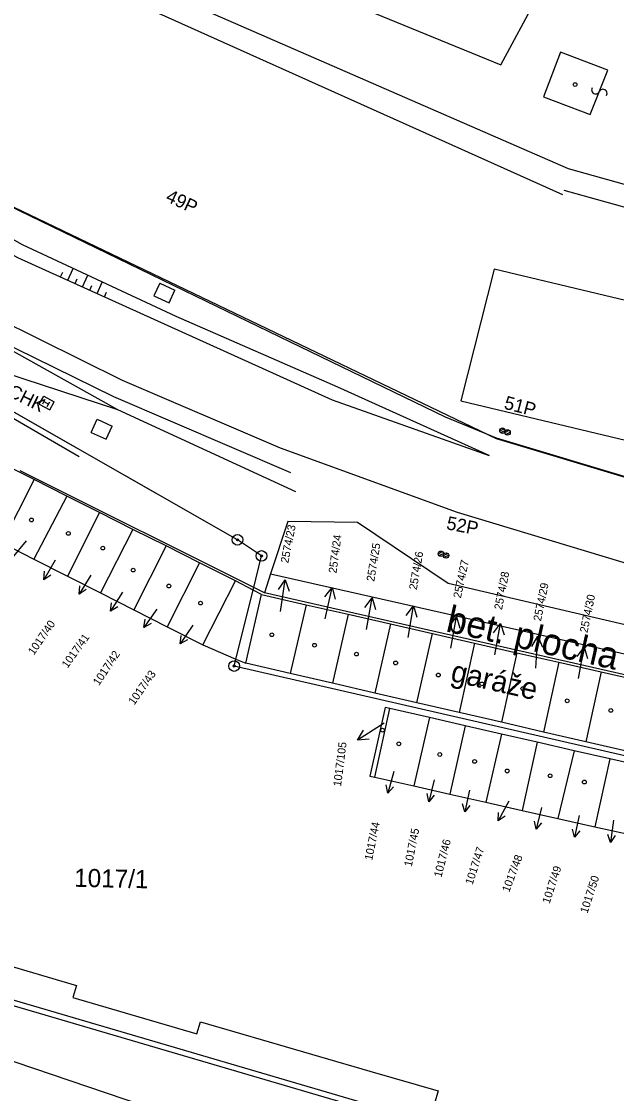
# Model space of a CAD drawing. Extents: x -469926 to -462499, y -1098642 to -1092733.
# Drawn here: x -465329.9 to -465274.2, y -1095180.8 to -1095080.4 of the extents above; entities that cross this region are included whole.
import ezdxf

# ---------------------------------------------------------------- set-up
doc = ezdxf.new("R2010")
doc.units = 0
for name, color, linetype in [('Vrstva 1', 7, 'Continuous'), ('Vrstva 10', 7, 'Continuous'), ('Vrstva 11', 7, 'Continuous'), ('Vrstva 12', 7, 'Continuous'), ('Vrstva 13', 7, 'Continuous'), ('Vrstva 16', 7, 'Continuous'), ('Vrstva 24', 7, 'Continuous'), ('Vrstva 25', 7, 'Continuous'), ('Vrstva 29', 7, 'Continuous'), ('Vrstva 4', 7, 'Continuous'), ('Vrstva 40', 7, 'Continuous'), ('Vrstva 42', 7, 'Continuous'), ('Vrstva 48', 7, 'Continuous'), ('Vrstva 50', 7, 'Continuous'), ('Vrstva 51', 7, 'Continuous'), ('Vrstva 6', 7, 'Continuous'), ('Vrstva 60', 7, 'Continuous'), ('Vrstva 8', 7, 'Continuous'), ('Vrstva 9', 7, 'Continuous')]:
    doc.layers.add(name, color=color, linetype=linetype)

msp = doc.modelspace()

# ---------------------------------------------------------------- linework, layer by layer
at = {"layer": 'Vrstva 1'}
for p, q in [((-465285.45, -1095119.46), (-465346.23, -1095090.29)), ((-465285.68, -1095103.56), (-465288.78, -1095115.91)), ((-465249.74, -1095112.21), (-465285.68, -1095103.56)), ((-465309.7, -1095128.93), (-465352.37, -1095104.57)), ((-465288.78, -1095115.91), (-465252.8, -1095124.51)), ((-465266.34, -1095125.23), (-465285.45, -1095119.46)), ((-465328.75, -1095123.29), (-465331.8, -1095121.75)), ((-465328.75, -1095123.29), (-465331.74, -1095129.22)), ((-465325.67, -1095124.83), (-465328.75, -1095123.29)), ((-465325.67, -1095124.83), (-465328.76, -1095130.73)), ((-465322.62, -1095126.37), (-465325.67, -1095124.83)), ((-465322.62, -1095126.37), (-465325.61, -1095132.34)), ((-465319.49, -1095127.95), (-465322.62, -1095126.37)), ((-465319.49, -1095127.95), (-465322.52, -1095133.91)), ((-465316.38, -1095129.51), (-465319.49, -1095127.95)), ((-465331.74, -1095129.22), (-465328.76, -1095130.73)), ((-465316.38, -1095129.51), (-465319.41, -1095135.49)), ((-465313.26, -1095131.08), (-465316.38, -1095129.51)), ((-465307.46, -1095130.44), (-465309.7, -1095128.93)), ((-465308.25, -1095133.64), (-465307.46, -1095130.44)), ((-465328.76, -1095130.73), (-465325.61, -1095132.34)), ((-465313.26, -1095131.08), (-465316.3, -1095137.07)), ((-465309.89, -1095132.78), (-465313.26, -1095131.08)), ((-465325.61, -1095132.34), (-465322.52, -1095133.91)), ((-465312.94, -1095138.78), (-465309.89, -1095132.78)), ((-465309.86, -1095140.1), (-465308.25, -1095133.64)), ((-465322.52, -1095133.91), (-465319.41, -1095135.49)), ((-465308.93, -1095140.5), (-465307.45, -1095134.06)), ((-465307.45, -1095134.06), (-465303.28, -1095135.01)), ((-465319.41, -1095135.49), (-465316.3, -1095137.07)), ((-465303.28, -1095135.01), (-465304.76, -1095141.46)), ((-465303.28, -1095135.01), (-465299.33, -1095135.91)), ((-465299.33, -1095135.91), (-465300.81, -1095142.37)), ((-465299.33, -1095135.91), (-465295.39, -1095136.81)), ((-465316.3, -1095137.07), (-465312.94, -1095138.78)), ((-465295.39, -1095136.81), (-465296.86, -1095143.29)), ((-465295.39, -1095136.81), (-465291.45, -1095137.71)), ((-465292.9, -1095144.2), (-465291.45, -1095137.71)), ((-465291.45, -1095137.71), (-465287.5, -1095138.61)), ((-465287.5, -1095138.61), (-465288.95, -1095145.11)), ((-465287.5, -1095138.61), (-465283.56, -1095139.51)), ((-465283.56, -1095139.51), (-465285, -1095146.02)), ((-465283.56, -1095139.51), (-465279.61, -1095140.41)), ((-465310.02, -1095140.76), (-465309.86, -1095140.1)), ((-465304.76, -1095141.46), (-465308.93, -1095140.5)), ((-465279.61, -1095140.41), (-465281.05, -1095146.94)), ((-465279.61, -1095140.41), (-465275.67, -1095141.31)), ((-465219.72, -1095161.52), (-465310.02, -1095140.76)), ((-465300.81, -1095142.37), (-465304.76, -1095141.46)), ((-465275.67, -1095141.31), (-465277.1, -1095147.85)), ((-465275.67, -1095141.31), (-465271.73, -1095142.21)), ((-465296.86, -1095143.29), (-465300.81, -1095142.37)), ((-465292.9, -1095144.2), (-465296.86, -1095143.29)), ((-465295.87, -1095144.64), (-465297.3, -1095151.07)), ((-465295.43, -1095144.74), (-465295.87, -1095144.64)), ((-465288.95, -1095145.11), (-465292.9, -1095144.2)), ((-465296.86, -1095151.17), (-465295.43, -1095144.74)), ((-465291.73, -1095145.59), (-465295.43, -1095144.74)), ((-465291.73, -1095145.59), (-465293.2, -1095151.99)), ((-465288.38, -1095146.35), (-465291.73, -1095145.59)), ((-465285, -1095146.02), (-465288.95, -1095145.11)), ((-465288.38, -1095146.35), (-465289.82, -1095152.76)), ((-465285, -1095147.13), (-465288.38, -1095146.35)), ((-465281.05, -1095146.94), (-465285, -1095146.02)), ((-465285, -1095147.13), (-465286.44, -1095153.52)), ((-465281.65, -1095147.89), (-465285, -1095147.13)), ((-465277.1, -1095147.85), (-465281.05, -1095146.94)), ((-465281.65, -1095147.89), (-465283.04, -1095154.29)), ((-465278.19, -1095148.69), (-465281.65, -1095147.89)), ((-465278.19, -1095148.69), (-465279.7, -1095155.04)), ((-465278.19, -1095148.69), (-465279.7, -1095155.04)), ((-465274.83, -1095149.46), (-465278.19, -1095148.69)), ((-465274.83, -1095149.46), (-465278.19, -1095148.69)), ((-465273.15, -1095148.76), (-465277.1, -1095147.85)), ((-465273.15, -1095148.76), (-465277.1, -1095147.85)), ((-465274.83, -1095149.46), (-465276.24, -1095155.82)), ((-465274.83, -1095149.46), (-465276.24, -1095155.82)), ((-465271.43, -1095150.24), (-465274.83, -1095149.46)), ((-465271.43, -1095150.24), (-465274.83, -1095149.46)), ((-465297.3, -1095151.07), (-465296.86, -1095151.17)), ((-465296.86, -1095151.17), (-465293.2, -1095151.99)), ((-465293.2, -1095151.99), (-465289.82, -1095152.76)), ((-465289.82, -1095152.76), (-465286.44, -1095153.52)), ((-465286.44, -1095153.52), (-465283.04, -1095154.29)), ((-465283.04, -1095154.29), (-465279.7, -1095155.04)), ((-465283.04, -1095154.29), (-465279.7, -1095155.04)), ((-465279.7, -1095155.04), (-465276.24, -1095155.82)), ((-465279.7, -1095155.04), (-465276.24, -1095155.82)), ((-465276.24, -1095155.82), (-465272.83, -1095156.59)), ((-465276.24, -1095155.82), (-465272.83, -1095156.59)), ((-465336.84, -1095167.15), (-465324.77, -1095170.68)), ((-465324.77, -1095170.68), (-465325.11, -1095171.83)), ((-465325.11, -1095171.83), (-465313.51, -1095175.23)), ((-465313.51, -1095175.23), (-465313.17, -1095174.09)), ((-465313.51, -1095175.23), (-465313.17, -1095174.09)), ((-465313.17, -1095174.09), (-465306.75, -1095175.96)), ((-465313.17, -1095174.09), (-465306.75, -1095175.96)), ((-465306.75, -1095175.96), (-465297.32, -1095178.72)), ((-465306.75, -1095175.96), (-465297.32, -1095178.72)), ((-465297.32, -1095178.72), (-465290.92, -1095180.57)), ((-465297.32, -1095178.72), (-465290.92, -1095180.57)), ((-465290.92, -1095180.57), (-465291.27, -1095181.74)), ((-465290.92, -1095180.57), (-465291.27, -1095181.74))]:
    msp.add_line(p, q, dxfattribs=at)
at = {"layer": 'Vrstva 10'}
msp.add_lwpolyline([(-465135.98, -1095170.77), (-465139.71, -1095170.75), (-465139.73, -1095170.89), (-465144.3, -1095170.27), (-465144.4, -1095170.93), (-465145.96, -1095170.72), (-465150.93, -1095170.7), (-465150.93, -1095170.7), (-465150.93, -1095170.7), (-465207.61, -1095162.89), (-465219.72, -1095161.52), (-465219.72, -1095161.52), (-465219.72, -1095161.52), (-465310.02, -1095140.76), (-465308.25, -1095133.64), (-465307.46, -1095130.44), (-465309.7, -1095128.93), (-465352.37, -1095104.57)], dxfattribs=at)
at = {"layer": 'Vrstva 11'}
for p, q in [((-465316.99, -1095104.89), (-465317.53, -1095106.08)), ((-465316.99, -1095104.89), (-465315.58, -1095105.54)), ((-465317.53, -1095106.08), (-465316.1, -1095106.73)), ((-465316.1, -1095106.73), (-465315.58, -1095105.54)), ((-465328.26, -1095116.21), (-465327.85, -1095115.46)), ((-465327.85, -1095115.46), (-465326.86, -1095116.01)), ((-465328.26, -1095116.21), (-465327.27, -1095116.75)), ((-465327.94, -1095116.19), (-465327.7, -1095115.76)), ((-465327.82, -1095115.98), (-465327.38, -1095116.22)), ((-465327.51, -1095116.44), (-465327.26, -1095116)), ((-465327.27, -1095116.75), (-465326.86, -1095116.01)), ((-465323.4, -1095118.86), (-465322.85, -1095117.63)), ((-465322.85, -1095117.63), (-465321.44, -1095118.27)), ((-465322, -1095119.5), (-465321.44, -1095118.27)), ((-465285.14, -1095118.72), (-465284.75, -1095118.52)), ((-465323.4, -1095118.86), (-465322, -1095119.5)), ((-465285.07, -1095118.89), (-465284.65, -1095118.68)), ((-465284.67, -1095118.87), (-465284.27, -1095118.67)), ((-465284.6, -1095119.05), (-465284.17, -1095118.83)), ((-465290.91, -1095130.24), (-465290.51, -1095130.04)), ((-465290.84, -1095130.41), (-465290.41, -1095130.2)), ((-465290.43, -1095130.4), (-465290.03, -1095130.2)), ((-465290.36, -1095130.57), (-465289.94, -1095130.36))]:
    msp.add_line(p, q, dxfattribs=at)
for centre in [(-465284.9, -1095118.71), (-465284.9, -1095118.71), (-465284.42, -1095118.87), (-465284.42, -1095118.87), (-465290.66, -1095130.24), (-465290.66, -1095130.24), (-465290.18, -1095130.4), (-465290.18, -1095130.4)]:
    msp.add_circle(centre, 0.25, dxfattribs=at)
at = {"layer": 'Vrstva 12'}
for p, q in [((-465312.61, -1095106.59), (-465340.64, -1095093.02)), ((-465290.24, -1095117.45), (-465312.61, -1095106.59)), ((-465285.45, -1095119.42), (-465290.24, -1095117.45)), ((-465266.36, -1095125.13), (-465285.45, -1095119.42))]:
    msp.add_line(p, q, dxfattribs=at)
at = {"layer": 'Vrstva 13'}
for p, q in [((-465304.98, -1095127.21), (-465306.61, -1095132.13)), ((-465298.47, -1095127.31), (-465304.98, -1095127.21)), ((-465289.98, -1095133.04), (-465298.47, -1095127.31)), ((-465306.61, -1095132.13), (-465307.17, -1095133.91)), ((-465306.61, -1095132.13), (-465232.1, -1095148.97)), ((-465231.51, -1095146.66), (-465289.98, -1095133.04))]:
    msp.add_line(p, q, dxfattribs=at)
at = {"layer": 'Vrstva 16'}
for p, q in [((-465329.5, -1095129.02), (-465330.82, -1095130.65)), ((-465326.77, -1095130.85), (-465327.83, -1095132.67)), ((-465323.43, -1095132.23), (-465324.53, -1095134.02)), ((-465305.67, -1095135.64), (-465305.23, -1095132.67)), ((-465301.51, -1095136.32), (-465300.83, -1095133.4)), ((-465320.46, -1095133.83), (-465321.58, -1095135.61)), ((-465297.64, -1095137.33), (-465297.11, -1095134.38)), ((-465317.24, -1095135.44), (-465318.47, -1095137.14)), ((-465293.72, -1095138.07), (-465293.24, -1095135.11)), ((-465289.73, -1095139.09), (-465289.2, -1095136.14)), ((-465313.9, -1095136.93), (-465315.06, -1095138.68)), ((-465285.6, -1095139.71), (-465285.07, -1095136.76)), ((-465281.76, -1095140.96), (-465281.59, -1095137.97)), ((-465277.77, -1095141.93), (-465277.24, -1095138.98)), ((-465295.96, -1095146.1), (-465298.48, -1095147.72)), ((-465295.07, -1095150.63), (-465295.62, -1095152.66)), ((-465291.28, -1095151.43), (-465291.79, -1095153.47)), ((-465287.99, -1095152.38), (-465288.43, -1095154.43)), ((-465284.29, -1095153.42), (-465285.29, -1095155.27)), ((-465284.29, -1095153.42), (-465285.29, -1095155.27)), ((-465281.24, -1095154.01), (-465281.73, -1095156.05)), ((-465281.24, -1095154.01), (-465281.73, -1095156.05)), ((-465277.71, -1095154.75), (-465278.15, -1095156.8)), ((-465277.71, -1095154.75), (-465278.15, -1095156.8)), ((-465274.5, -1095155.2), (-465274.78, -1095157.28)), ((-465274.5, -1095155.2), (-465274.78, -1095157.28))]:
    msp.add_line(p, q, dxfattribs=at)
for points in [[(-465327.17, -1095132.24), (-465327.83, -1095132.67), (-465327.78, -1095131.88)], [(-465323.87, -1095133.6), (-465324.53, -1095134.02), (-465324.46, -1095133.24)], [(-465305.87, -1095133.59), (-465305.23, -1095132.67), (-465304.88, -1095133.74)], [(-465301.54, -1095134.26), (-465300.83, -1095133.4), (-465300.57, -1095134.49)], [(-465297.78, -1095135.27), (-465297.11, -1095134.38), (-465296.79, -1095135.45)], [(-465320.91, -1095135.2), (-465321.58, -1095135.61), (-465321.5, -1095134.83)], [(-465293.9, -1095136.02), (-465293.24, -1095135.11), (-465292.91, -1095136.18)], [(-465317.78, -1095136.78), (-465318.47, -1095137.14), (-465318.34, -1095136.37)], [(-465289.87, -1095137.03), (-465289.2, -1095136.14), (-465288.88, -1095137.21)], [(-465285.74, -1095137.65), (-465285.07, -1095136.76), (-465284.75, -1095137.83)], [(-465314.38, -1095138.29), (-465315.06, -1095138.68), (-465314.97, -1095137.9)], [(-465282.15, -1095138.94), (-465281.59, -1095137.97), (-465281.15, -1095138.99)], [(-465277.91, -1095139.87), (-465277.24, -1095138.98), (-465276.92, -1095140.05)], [(-465297.37, -1095147.6), (-465298.48, -1095147.72), (-465297.91, -1095146.76)], [(-465295.1, -1095152.07), (-465295.62, -1095152.66), (-465295.77, -1095151.89)], [(-465291.28, -1095152.87), (-465291.79, -1095153.47), (-465291.96, -1095152.7)], [(-465287.94, -1095153.82), (-465288.43, -1095154.43), (-465288.63, -1095153.68)], [(-465284.65, -1095154.82), (-465285.29, -1095155.27), (-465285.26, -1095154.49)], [(-465284.65, -1095154.82), (-465285.29, -1095155.27), (-465285.26, -1095154.49)], [(-465281.23, -1095155.45), (-465281.73, -1095156.05), (-465281.91, -1095155.29)], [(-465281.23, -1095155.45), (-465281.73, -1095156.05), (-465281.91, -1095155.29)], [(-465277.66, -1095156.19), (-465278.15, -1095156.8), (-465278.35, -1095156.04)], [(-465277.66, -1095156.19), (-465278.15, -1095156.8), (-465278.35, -1095156.04)], [(-465274.34, -1095156.63), (-465274.78, -1095157.28), (-465275.04, -1095156.54)], [(-465274.34, -1095156.63), (-465274.78, -1095157.28), (-465275.04, -1095156.54)]]:
    msp.add_lwpolyline(points, dxfattribs=at)
at = {"layer": 'Vrstva 24'}
for centre, radius in [((-465309.7, -1095128.93), 0.5), ((-465309.7, -1095128.93), 0.1), ((-465307.46, -1095130.44), 0.5), ((-465307.46, -1095130.44), 0.1), ((-465310.02, -1095140.76), 0.5), ((-465310.02, -1095140.76), 0.1)]:
    msp.add_circle(centre, radius, dxfattribs=at)
at = {"layer": 'Vrstva 25'}
for centre in [(-465329, -1095127.07), (-465325.54, -1095128.33), (-465322.32, -1095129.71), (-465319.47, -1095131.77), (-465316.13, -1095133.26), (-465313.16, -1095134.86), (-465306.48, -1095137.83), (-465302.49, -1095138.81), (-465298.57, -1095139.64), (-465294.9, -1095140.47), (-465290.9, -1095141.6), (-465286.83, -1095142.43), (-465282.99, -1095142.88), (-465278.83, -1095144.02), (-465274.75, -1095144.92), (-465296.12, -1095146.77), (-465294.6, -1095148.05), (-465290.77, -1095149.05), (-465287.5, -1095149.7), (-465284.45, -1095150.59), (-465280.44, -1095151.04), (-465280.44, -1095151.04), (-465277.23, -1095151.63), (-465277.23, -1095151.63)]:
    msp.add_circle(centre, 0.175, dxfattribs=at)
at = {"layer": 'Vrstva 29'}
msp.add_circle((-465278.1, -1095086.27), 0.175, dxfattribs=at)
at = {"layer": 'Vrstva 4'}
for p, q in [((-465310.53, -1095073.95), (-465285.06, -1095084.43)), ((-465285.06, -1095084.43), (-465280.07, -1095075.13)), ((-465279.46, -1095083.24), (-465281.05, -1095087.41)), ((-465275.04, -1095084.93), (-465279.46, -1095083.24)), ((-465276.67, -1095089.08), (-465275.04, -1095084.93)), ((-465281.05, -1095087.41), (-465276.67, -1095089.08)), ((-465308.25, -1095133.64), (-465309.89, -1095132.78)), ((-465307.45, -1095134.06), (-465308.25, -1095133.64)), ((-465312.94, -1095138.78), (-465309.86, -1095140.1)), ((-465309.86, -1095140.1), (-465308.93, -1095140.5)), ((-465189.34, -1095214.13), (-465355.8, -1095165.21))]:
    msp.add_line(p, q, dxfattribs=at)
at = {"layer": 'Vrstva 40'}
for p, q in [((-465339.74, -1095067.5), (-465278.76, -1095094.15)), ((-465278.76, -1095094.15), (-465241.79, -1095104.38))]:
    msp.add_line(p, q, dxfattribs=at)
at = {"layer": 'Vrstva 42'}
for p, q in [((-465279.24, -1095096.59), (-465339.95, -1095069.31)), ((-465241.12, -1095106.74), (-465279.11, -1095096.2))]:
    msp.add_line(p, q, dxfattribs=at)
at = {"layer": 'Vrstva 48'}
for p, q in [((-465326.26, -1095104.29), (-465326.06, -1095103.85)), ((-465325.58, -1095104.6), (-465325.09, -1095103.51)), ((-465324.9, -1095104.91), (-465324.7, -1095104.48)), ((-465324.21, -1095105.22), (-465323.73, -1095104.14)), ((-465323.53, -1095105.53), (-465323.34, -1095105.1)), ((-465322.85, -1095105.84), (-465322.37, -1095104.78)), ((-465322.16, -1095106.15), (-465321.97, -1095105.73))]:
    msp.add_line(p, q, dxfattribs=at)
at = {"layer": 'Vrstva 51'}
for centre, radius, start, end in [((-465276.17, -1095086.77), 0.376, 148.4604, 334.7715), ((-465275.48, -1095087.09), 0.377, 327.7843, 155.4475)]:
    msp.add_arc(centre, radius, start, end, dxfattribs=at)
at = {"layer": 'Vrstva 6'}
for p, q in [((-465307.17, -1095133.91), (-465330.06, -1095122.47)), ((-465232.58, -1095150.91), (-465307.17, -1095133.91)), ((-465181.83, -1095228.27), (-465368.22, -1095165.09))]:
    msp.add_line(p, q, dxfattribs=at)
for points in [[(-465542.65, -1094856.19), (-465523.91, -1094883.75), (-465506.3, -1094909.59), (-465490.33, -1094932.99), (-465474.43, -1094956.03), (-465442.6, -1095002.04), (-465429.69, -1095019.75), (-465428.49, -1095021.29), (-465416.22, -1095035.84), (-465398.61, -1095054.41), (-465391.85, -1095060.09), (-465391.38, -1095060.44), (-465363.84, -1095082.26), (-465348.99, -1095091.83), (-465330.29, -1095102.47), (-465300.84, -1095115.8), (-465286.15, -1095121.03)], [(-465324.52, -1095121.16), (-465355.23, -1095103.31), (-465366.7, -1095096.22), (-465388.26, -1095080.92), (-465407.46, -1095064.39), (-465410.74, -1095061.49), (-465438.84, -1095028.81), (-465471.05, -1094987.83), (-465484.21, -1094964), (-465501.26, -1094940.2), (-465517.87, -1094916.99), (-465530.49, -1094898.64), (-465543.12, -1094880.29)], [(-465286.15, -1095121.03), (-465300.31, -1095114.64), (-465315.43, -1095108.01), (-465329.83, -1095101.3), (-465349.76, -1095089.95), (-465363.54, -1095081.26), (-465376.66, -1095070.9), (-465389.77, -1095060.53), (-465397.62, -1095054.11), (-465404.68, -1095046.84), (-465415.44, -1095034.93), (-465426.3, -1095022.59), (-465441.64, -1095001.08), (-465457.78, -1094978.4), (-465473.91, -1094955.71), (-465488.32, -1094935.9)], [(-465452.58, -1095007.67), (-465452.58, -1095007.67), (-465435.49, -1095028.45), (-465422.3, -1095043.6), (-465409.18, -1095058.69), (-465389.92, -1095076.25), (-465386.62, -1095079.19), (-465381.22, -1095082.72), (-465368.89, -1095090.97), (-465354.37, -1095101.9), (-465335.17, -1095112.06), (-465320.93, -1095116.71), (-465304.27, -1095124.41)], [(-465304.71, -1095122.66), (-465321.28, -1095115.52), (-465335.97, -1095108.31), (-465320.93, -1095116.71)]]:
    msp.add_lwpolyline(points, dxfattribs=at)
at = {"layer": 'Vrstva 60'}
for p, q in [((-465320.48, -1095114), (-465335.97, -1095106.3)), ((-465305.67, -1095120.33), (-465320.48, -1095114)), ((-465289.12, -1095126.36), (-465305.67, -1095120.33)), ((-465271.12, -1095131.82), (-465289.12, -1095126.36))]:
    msp.add_line(p, q, dxfattribs=at)
at = {"layer": 'Vrstva 8'}
msp.add_line((-465179.3, -1095216.47), (-465368.14, -1095161.1), dxfattribs=at)

# ---------------------------------------------------------------- texts
at = {"layer": 'Vrstva 11'}
for s, rotation, p in [('49P', 334.8385, (-465316.51, -1095097.16)), ('116CHK', 333.5683, (-465333.8, -1095114.18)), ('51P', 345.3614, (-465284.83, -1095116.63)), ('52P', 348.8653, (-465290.21, -1095127.93))]:
    msp.add_text(s, height=1.25, rotation=rotation, dxfattribs=at).set_placement(p)
at = {"layer": 'Vrstva 13'}
msp.add_text('bet. plocha', height=2.5, rotation=347.1579, dxfattribs=at).set_placement((-465290.29, -1095137.49))
at = {"layer": 'Vrstva 50'}
for s, height, rotation, p in [('2574/23', 0.75, 78.786, (-465304.95, -1095131.16)), ('2574/24', 0.75, 82.395, (-465300.44, -1095132.1)), ('2574/25', 0.75, 80.676, (-465296.9, -1095132.88)), ('2574/26', 0.75, 80.271, (-465292.92, -1095133.66)), ('2574/27', 0.75, 77.922, (-465288.79, -1095134.45)), ('2574/28', 0.75, 78.957, (-465284.95, -1095135.54)), ('2574/29', 0.75, 78.498, (-465281.29, -1095136.6)), ('2574/30', 0.75, 78.327, (-465276.94, -1095137.69)), ('1017/40', 0.75, 55.575, (-465328.77, -1095139.79)), ('1017/41', 0.75, 54.549, (-465325.62, -1095141.02)), ('1017/42', 0.75, 56.205, (-465322.68, -1095142.65)), ('1017/43', 0.75, 55.116, (-465319.37, -1095144.47)), ('1017/105', 0.75, 82.791, (-465300.01, -1095152.07)), ('1017/44', 0.75, 78.669, (-465297.09, -1095159.01)), ('1017/45', 0.75, 78.669, (-465293.39, -1095159.6)), ('1017/46', 0.75, 75.744, (-465290.61, -1095160.61)), ('1017/47', 0.75, 72.018, (-465287.7, -1095161.31)), ('1017/48', 0.75, 69.273, (-465284.27, -1095162.01)), ('1017/1', 1.7, 358.785, (-465325.01, -1095161.44)), ('1017/49', 0.75, 71.793, (-465280.49, -1095163.08)), ('1017/50', 0.75, 72.018, (-465276.94, -1095163.99))]:
    msp.add_text(s, height=height, rotation=rotation, dxfattribs=at).set_placement(p)
at = {"layer": 'Vrstva 9'}
msp.add_text('garáže', height=2, rotation=347.1609, dxfattribs=at).set_placement((-465289.84, -1095142.15))

doc.saveas('drawing.dxf')
